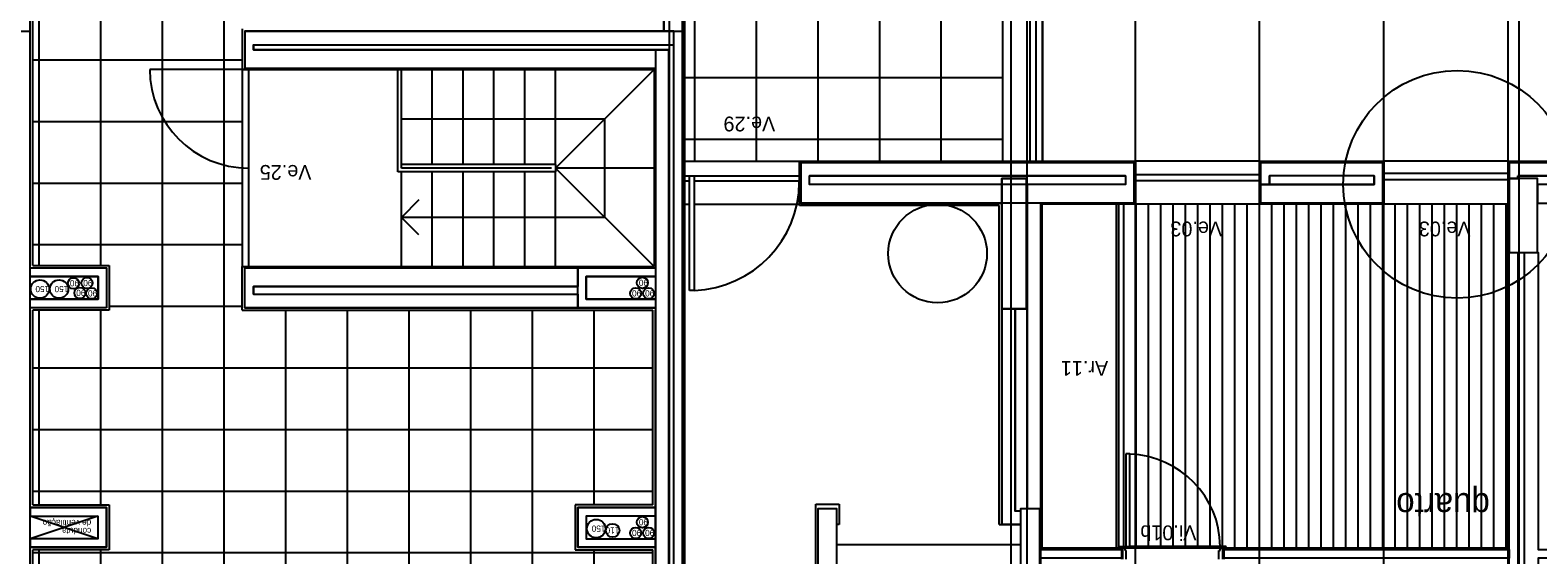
# Model space of a CAD drawing. Extents: x 1278 to 1356, y -253.7 to -224.
# Drawn here: x 1291.33 to 1303.56, y -235.12 to -230.86 of the extents above; entities that cross this region are included whole.
import ezdxf

# ---------------------------------------------------------------- set-up
doc = ezdxf.new("R2010")
doc.units = 0
for name, color, linetype in [('Level 1', 7, 'Continuous'), ('Level 10', 7, 'Continuous'), ('Level 13', 7, 'Continuous'), ('Level 2', 7, 'Continuous'), ('Level 21', 7, 'Continuous'), ('Level 25', 7, 'Continuous'), ('Level 3', 7, 'Continuous'), ('Level 4', 7, 'Continuous'), ('Level 40', 7, 'Continuous'), ('Level 41', 7, 'Continuous'), ('Level 60', 7, 'Continuous'), ('Level 65', 7, 'Continuous'), ('Level 66', 7, 'Continuous'), ('Level 67', 7, 'Continuous'), ('Level 69', 7, 'Continuous'), ('Level 70', 7, 'Continuous'), ('Level 93', 7, 'Continuous')]:
    doc.layers.add(name, color=color, linetype=linetype)

msp = doc.modelspace()

# ---------------------------------------------------------------- linework, layer by layer
at = {"layer": 'Level 1'}
for p, q in [((1291.334, -239.254), (1291.334, -228.594)), ((1296.473, -228.594), (1296.473, -230.87)), ((1296.623, -236.569), (1296.623, -228.594)), ((1287.754, -230.87), (1291.334, -230.87)), ((1293.074, -230.87), (1296.623, -230.87)), ((1293.074, -230.87), (1293.074, -231.17)), ((1296.553, -236.639), (1296.553, -230.87)), ((1293.144, -230.98), (1296.553, -230.98)), ((1293.144, -230.98), (1293.144, -231.02)), ((1293.144, -231.02), (1296.514, -231.02)), ((1296.404, -231.02), (1296.404, -233.134)), ((1296.514, -231.02), (1296.514, -232.974)), ((1293.074, -231.17), (1296.404, -231.17)), ((1297.583, -232.264), (1297.583, -231.934)), ((1300.287, -231.934), (1300.287, -232.264)), ((1301.314, -231.934), (1302.302, -231.934)), ((1301.314, -232.264), (1301.314, -231.934)), ((1302.302, -231.934), (1302.302, -232.264)), ((1303.329, -231.934), (1304.317, -231.934)), ((1297.653, -232.114), (1297.653, -232.044)), ((1300.217, -232.044), (1300.217, -232.114)), ((1301.384, -232.114), (1301.384, -232.044)), ((1302.232, -232.044), (1302.232, -232.114)), ((1303.399, -232.064), (1303.399, -232.044)), ((1299.213, -232.264), (1297.583, -232.264)), ((1299.213, -234.874), (1299.213, -232.264)), ((1300.287, -232.264), (1299.213, -232.264)), ((1299.42, -234.744), (1299.42, -232.264)), ((1302.302, -232.264), (1301.314, -232.264)), ((1293.074, -232.79), (1296.404, -232.79)), ((1293.074, -233.114), (1293.074, -232.79)), ((1293.144, -232.94), (1295.774, -232.94)), ((1293.144, -233.004), (1293.144, -232.94)), ((1293.144, -233.004), (1295.774, -233.004)), ((1296.514, -236.689), (1296.514, -232.974)), ((1293.074, -233.114), (1296.404, -233.114)), ((1296.404, -236.799), (1296.404, -233.134)), ((1299.324, -234.764), (1299.324, -233.121)), ((1299.369, -234.874), (1299.213, -234.874)), ((1299.369, -234.764), (1299.323, -234.764)), ((1300.183, -235.075), (1299.53, -235.075)), ((1300.183, -235.065), (1300.183, -235.155)), ((1301.013, -235.065), (1301.013, -235.075)), ((1301.013, -235.065), (1301.013, -235.155))]:
    msp.add_line(p, q, dxfattribs=at)
msp.add_lwpolyline([(1303.329, -235.075), (1301.013, -235.075)], dxfattribs=at)
at = {"layer": 'Level 10'}
for p, q in [((1300.204, -235.065), (1300.204, -232.274)), ((1300.304, -235.065), (1300.304, -232.274)), ((1300.404, -235.065), (1300.404, -232.274)), ((1300.504, -235.065), (1300.504, -232.274)), ((1300.604, -235.065), (1300.604, -232.274)), ((1300.704, -235.065), (1300.704, -232.274)), ((1300.804, -235.065), (1300.804, -232.274)), ((1300.904, -235.065), (1300.904, -232.274)), ((1301.004, -235.065), (1301.004, -232.274)), ((1301.104, -235.065), (1301.104, -232.274)), ((1301.204, -235.065), (1301.204, -232.274)), ((1301.304, -235.065), (1301.304, -232.274)), ((1301.404, -235.065), (1301.404, -232.274)), ((1301.504, -235.065), (1301.504, -232.274)), ((1301.604, -235.065), (1301.604, -232.274)), ((1301.704, -235.065), (1301.704, -232.274)), ((1301.804, -235.065), (1301.804, -232.274)), ((1301.904, -235.065), (1301.904, -232.274)), ((1302.004, -235.065), (1302.004, -232.274)), ((1302.104, -235.065), (1302.104, -232.274)), ((1302.204, -235.065), (1302.204, -232.274)), ((1302.304, -235.065), (1302.304, -232.274)), ((1302.404, -235.065), (1302.404, -232.274)), ((1302.504, -235.065), (1302.504, -232.274)), ((1302.604, -235.065), (1302.604, -232.274)), ((1302.704, -235.065), (1302.704, -232.274)), ((1302.804, -235.065), (1302.804, -232.274)), ((1302.904, -235.065), (1302.904, -232.274)), ((1303.004, -235.065), (1303.004, -232.274)), ((1303.104, -235.065), (1303.104, -232.274)), ((1303.204, -235.065), (1303.204, -232.274)), ((1303.304, -235.065), (1303.304, -232.274)), ((1300.983, -235.065), (1300.213, -235.065))]:
    msp.add_line(p, q, dxfattribs=at)
at = {"layer": 'Level 13'}
for p, q in [((1293.104, -231.18), (1292.304, -231.18)), ((1293.054, -231.18), (1293.054, -232.78)), ((1293.104, -231.18), (1293.104, -232.78)), ((1300.143, -235.065), (1300.143, -232.274)), ((1300.163, -235.065), (1300.163, -232.274)), ((1300.218, -234.3), (1300.218, -235.05)), ((1300.253, -234.3), (1300.218, -234.3)), ((1300.253, -235.05), (1300.253, -234.3)), ((1300.163, -235.05), (1300.213, -235.05)), ((1300.163, -235.06), (1300.163, -235.05)), ((1300.168, -235.06), (1300.163, -235.06)), ((1300.168, -235.065), (1300.168, -235.06)), ((1300.213, -235.065), (1300.168, -235.065)), ((1300.193, -235.065), (1300.193, -235.155)), ((1300.213, -235.065), (1300.193, -235.065)), ((1300.213, -235.05), (1300.213, -235.065)), ((1300.213, -235.085), (1300.213, -235.065)), ((1300.223, -235.085), (1300.213, -235.085)), ((1300.218, -235.05), (1300.253, -235.05)), ((1300.223, -235.155), (1300.223, -235.085)), ((1300.973, -235.155), (1300.973, -235.085)), ((1300.973, -235.085), (1300.983, -235.085)), ((1301.033, -235.05), (1300.983, -235.05)), ((1300.983, -235.05), (1300.983, -235.065)), ((1300.983, -235.085), (1300.983, -235.065)), ((1300.983, -235.065), (1301.003, -235.065)), ((1300.983, -235.065), (1301.028, -235.065)), ((1301.003, -235.065), (1301.003, -235.155)), ((1301.028, -235.065), (1301.028, -235.06)), ((1301.028, -235.06), (1301.033, -235.06)), ((1301.033, -235.06), (1301.033, -235.05))]:
    msp.add_line(p, q, dxfattribs=at)
msp.add_arc((1293.104, -231.18), 0.8, 180, 270, dxfattribs=at)
at = {"layer": 'Level 2'}
for p, q in [((1299.443, -231.924), (1299.443, -228.524)), ((1299.493, -231.924), (1299.493, -228.474)), ((1299.543, -231.924), (1299.543, -228.424)), ((1299.543, -228.424), (1299.543, -231.924)), ((1299.223, -231.924), (1299.223, -228.744)), ((1294.314, -232.01), (1294.314, -231.18)), ((1294.344, -231.98), (1294.344, -231.18)), ((1294.594, -231.95), (1294.594, -231.18)), ((1294.844, -231.95), (1294.844, -231.18)), ((1295.094, -231.95), (1295.094, -231.18)), ((1295.344, -231.95), (1295.344, -231.18)), ((1295.594, -231.95), (1295.594, -231.18)), ((1295.594, -231.98), (1296.394, -231.18)), ((1294.344, -231.58), (1295.994, -231.58)), ((1295.994, -232.38), (1295.994, -231.58)), ((1296.643, -231.924), (1297.573, -231.924)), ((1301.304, -231.924), (1300.297, -231.924)), ((1303.319, -231.924), (1302.312, -231.924)), ((1295.594, -232.01), (1294.314, -232.01)), ((1295.594, -231.95), (1294.344, -231.95)), ((1295.562, -231.98), (1294.344, -231.98)), ((1294.344, -232.78), (1294.344, -232.01)), ((1294.594, -232.78), (1294.594, -232.01)), ((1294.844, -232.78), (1294.844, -232.01)), ((1295.094, -232.78), (1295.094, -232.01)), ((1295.344, -232.78), (1295.344, -232.01)), ((1295.594, -231.95), (1295.594, -232.01)), ((1296.394, -231.98), (1295.594, -231.98)), ((1295.594, -231.98), (1296.394, -232.78)), ((1295.594, -232.78), (1295.594, -232.01)), ((1296.643, -232.044), (1297.573, -232.044)), ((1296.681, -232.974), (1296.681, -232.044)), ((1296.681, -232.044), (1296.721, -232.044)), ((1296.721, -232.974), (1296.721, -232.044)), ((1301.304, -232.034), (1300.297, -232.034)), ((1303.319, -232.024), (1302.312, -232.024)), ((1296.643, -232.084), (1296.681, -232.084)), ((1296.721, -232.084), (1297.573, -232.084)), ((1301.304, -232.084), (1300.297, -232.084)), ((1303.319, -232.074), (1302.312, -232.074)), ((1294.485, -232.239), (1294.344, -232.38)), ((1296.643, -232.274), (1296.681, -232.274)), ((1296.721, -232.274), (1297.573, -232.274)), ((1301.304, -232.274), (1300.297, -232.274)), ((1303.319, -232.274), (1302.312, -232.274)), ((1294.485, -232.522), (1294.344, -232.38)), ((1295.994, -232.38), (1294.344, -232.38)), ((1296.721, -232.974), (1296.681, -232.974)), ((1299.369, -235.039), (1297.873, -235.039))]:
    msp.add_line(p, q, dxfattribs=at)
msp.add_circle((1298.693, -232.674), 0.4, dxfattribs=at)
at = {"layer": 'Level 21'}
for p, q in [((1291.404, -228.744), (1291.404, -232.77)), ((1291.904, -228.744), (1291.904, -232.77)), ((1292.404, -228.744), (1292.404, -239.104)), ((1292.904, -228.744), (1292.904, -239.104)), ((1296.723, -231.924), (1296.723, -228.744)), ((1297.223, -231.924), (1297.223, -228.744)), ((1297.723, -231.924), (1297.723, -228.744)), ((1298.223, -231.924), (1298.223, -228.744)), ((1298.723, -231.924), (1298.723, -228.744)), ((1293.054, -231.104), (1291.354, -231.104)), ((1296.643, -231.244), (1299.223, -231.244)), ((1293.054, -231.604), (1291.354, -231.604)), ((1296.643, -231.744), (1299.223, -231.744)), ((1293.054, -232.104), (1291.354, -232.104)), ((1293.054, -232.604), (1291.354, -232.604)), ((1291.404, -233.134), (1291.404, -234.714)), ((1291.904, -233.134), (1291.904, -234.714)), ((1293.054, -233.104), (1291.974, -233.104)), ((1293.404, -233.134), (1293.404, -239.104)), ((1293.904, -233.134), (1293.904, -239.104)), ((1294.404, -233.134), (1294.404, -239.104)), ((1294.904, -233.134), (1294.904, -239.104)), ((1295.404, -233.134), (1295.404, -239.104)), ((1295.904, -233.134), (1295.904, -234.714)), ((1296.384, -233.604), (1291.354, -233.604)), ((1296.384, -234.104), (1291.354, -234.104)), ((1296.384, -234.604), (1291.354, -234.604)), ((1296.384, -235.104), (1291.354, -235.104)), ((1291.404, -235.078), (1291.404, -239.104)), ((1291.904, -235.078), (1291.904, -239.104)), ((1295.904, -235.078), (1295.904, -239.104))]:
    msp.add_line(p, q, dxfattribs=at)
at = {"layer": 'Level 25'}
msp.add_lwpolyline([(1299.213, -233.121), (1299.413, -233.121), (1299.413, -232.064), (1299.213, -232.064)], close=True, dxfattribs=at)
at = {"layer": 'Level 3'}
msp.add_ellipse((1296.68, -232.094), major_axis=(-0.891, 0), ratio=0.988242, start_param=1.616241, end_param=3.141592, dxfattribs=at)
at = {"layer": 'Level 4'}
msp.add_line((1300.983, -235.05), (1300.253, -235.05), dxfattribs=at)
msp.add_ellipse((1300.22, -235.05), major_axis=(-0.763, 0), ratio=0.982661, start_param=3.141593, end_param=4.668897, dxfattribs=at)
at = {"layer": 'Level 41'}
for p, q in [((1291.883, -234.988), (1291.334, -234.804)), ((1291.883, -234.804), (1291.334, -234.988))]:
    msp.add_line(p, q, dxfattribs=at)
for centre, radius in [((1291.413, -232.962), 0.075), ((1291.568, -232.962), 0.075), ((1291.685, -232.915), 0.045), ((1291.794, -232.913), 0.045), ((1296.299, -232.911), 0.045), ((1291.737, -232.993), 0.045), ((1291.832, -232.997), 0.045), ((1296.244, -232.997), 0.045), ((1296.35, -232.997), 0.045), ((1295.924, -234.906), 0.075), ((1296.057, -234.921), 0.055), ((1296.299, -234.854), 0.045), ((1296.244, -234.941), 0.045), ((1296.35, -234.941), 0.045)]:
    msp.add_circle(centre, radius, dxfattribs=at)
at = {"layer": 'Level 65'}
for p, q in [((1291.354, -232.77), (1291.354, -228.574)), ((1296.643, -236.545), (1296.643, -228.574)), ((1293.054, -230.85), (1293.054, -231.18)), ((1293.054, -231.18), (1296.394, -231.18)), ((1296.394, -231.18), (1296.394, -232.78)), ((1296.643, -231.924), (1300.297, -231.924)), ((1297.573, -232.284), (1297.573, -231.924)), ((1300.297, -231.924), (1300.297, -232.274)), ((1301.304, -232.274), (1301.304, -231.924)), ((1301.304, -231.924), (1302.312, -231.924)), ((1302.312, -231.924), (1302.312, -232.274)), ((1303.319, -231.924), (1304.327, -231.924)), ((1299.193, -232.284), (1297.573, -232.284)), ((1299.193, -234.874), (1299.193, -232.284)), ((1300.297, -232.274), (1299.54, -232.274)), ((1299.54, -235.065), (1299.54, -232.274)), ((1302.312, -232.274), (1301.304, -232.274)), ((1303.319, -235.065), (1303.319, -232.274)), ((1291.354, -232.77), (1291.974, -232.77)), ((1291.974, -232.77), (1291.974, -233.134)), ((1293.054, -232.78), (1296.394, -232.78)), ((1293.054, -233.134), (1293.054, -232.78)), ((1291.974, -233.134), (1291.354, -233.134)), ((1291.354, -234.714), (1291.354, -233.134)), ((1293.054, -233.134), (1296.384, -233.134)), ((1296.384, -234.714), (1296.384, -233.134)), ((1291.354, -234.714), (1291.973, -234.714)), ((1291.973, -234.714), (1291.973, -235.078)), ((1296.384, -234.714), (1295.754, -234.714)), ((1295.754, -234.714), (1295.754, -235.078)), ((1297.704, -234.708), (1297.894, -234.708)), ((1297.704, -236.545), (1297.704, -234.708)), ((1297.894, -234.708), (1297.894, -234.874)), ((1297.894, -234.874), (1297.873, -234.874)), ((1299.193, -234.874), (1299.213, -234.874)), ((1291.973, -235.078), (1291.354, -235.078)), ((1291.354, -239.274), (1291.354, -235.078)), ((1295.754, -235.078), (1296.384, -235.078)), ((1296.384, -236.819), (1296.384, -235.078)), ((1300.183, -235.065), (1299.54, -235.065))]:
    msp.add_line(p, q, dxfattribs=at)
msp.add_lwpolyline([(1303.319, -235.065), (1301.013, -235.065)], dxfattribs=at)
at = {"layer": 'Level 66'}
for p, q in [((1297.583, -231.934), (1300.287, -231.934)), ((1303.329, -235.075), (1303.329, -231.934)), ((1300.217, -232.044), (1297.653, -232.044)), ((1302.232, -232.044), (1301.384, -232.044)), ((1304.247, -232.044), (1303.399, -232.044)), ((1300.217, -232.114), (1297.653, -232.114)), ((1302.232, -232.114), (1301.384, -232.114)), ((1304.247, -232.114), (1303.559, -232.114)), ((1299.53, -243.584), (1299.53, -232.264)), ((1303.4, -236.221), (1303.4, -232.664)), ((1303.452, -236.221), (1303.452, -232.664)), ((1291.334, -232.79), (1291.954, -232.79)), ((1291.954, -232.79), (1291.954, -233.114)), ((1295.774, -233.114), (1295.774, -232.79)), ((1303.452, -236.352), (1303.452, -232.794)), ((1295.844, -233.044), (1295.844, -232.86)), ((1295.844, -232.86), (1296.404, -232.86)), ((1296.404, -233.044), (1295.844, -233.044)), ((1291.954, -233.114), (1291.334, -233.114)), ((1291.334, -234.734), (1291.953, -234.734)), ((1291.953, -234.734), (1291.953, -235.058)), ((1296.404, -234.734), (1295.774, -234.734)), ((1295.774, -234.734), (1295.774, -235.058)), ((1296.404, -234.804), (1295.844, -234.804)), ((1295.844, -234.804), (1295.844, -234.988)), ((1295.844, -234.988), (1296.404, -234.988)), ((1291.953, -235.058), (1291.334, -235.058)), ((1295.774, -235.058), (1296.404, -235.058))]:
    msp.add_line(p, q, dxfattribs=at)
for points in [[(1299.413, -233.121), (1299.213, -233.121), (1299.213, -232.064), (1299.413, -232.064)], [(1303.329, -232.664), (1303.559, -232.664), (1303.559, -232.064), (1303.329, -232.064)], [(1303.329, -232.664), (1303.559, -232.664), (1303.559, -232.064), (1303.329, -232.064)], [(1291.884, -233.044), (1291.334, -233.044), (1291.334, -232.86), (1291.884, -232.86)], [(1299.519, -234.744), (1299.519, -236.639), (1297.724, -236.639), (1297.724, -234.744), (1297.874, -234.744), (1297.874, -236.439), (1299.369, -236.439), (1299.369, -234.744)], [(1291.883, -234.988), (1291.334, -234.988), (1291.334, -234.804), (1291.883, -234.804)]]:
    msp.add_lwpolyline(points, close=True, dxfattribs=at)
at = {"layer": 'Level 67'}
msp.add_line((1296.404, -232.86), (1296.404, -233.044), dxfattribs=at)
for points in [[(1291.184, -239.254), (1291.334, -239.254), (1291.334, -228.594), (1291.184, -228.594), (1291.184, -230.87), (1291.224, -230.87), (1291.224, -233.114), (1291.184, -233.114)], [(1296.473, -230.87), (1296.473, -228.594), (1296.623, -228.594), (1296.623, -236.569), (1297.724, -236.569), (1297.724, -236.639), (1296.553, -236.639), (1296.553, -230.87)], [(1296.553, -230.87), (1293.074, -230.87), (1293.074, -231.17), (1296.404, -231.17), (1296.404, -236.799), (1299.181, -236.799), (1299.181, -243.914), (1301.224, -243.914), (1301.224, -243.584), (1299.519, -243.584), (1299.519, -243.734), (1301.154, -243.734), (1301.154, -243.804), (1299.291, -243.804), (1299.291, -236.689), (1296.514, -236.689), (1296.514, -231.17), (1296.514, -231.02), (1293.144, -231.02), (1293.144, -230.98), (1296.553, -230.98)], [(1299.42, -234.744), (1299.53, -234.744), (1299.53, -232.264), (1300.287, -232.264), (1300.287, -231.934), (1297.583, -231.934), (1297.583, -232.264), (1299.213, -232.264), (1299.213, -232.114), (1297.653, -232.114), (1297.653, -232.044), (1300.217, -232.044), (1300.217, -232.114), (1299.42, -232.114)], [(1302.302, -231.934), (1302.302, -232.264), (1301.314, -232.264), (1301.314, -232.114), (1302.232, -232.114), (1302.232, -232.044), (1301.384, -232.044), (1301.384, -232.114), (1301.314, -232.114), (1301.314, -231.934)], [(1303.399, -232.044), (1304.247, -232.044), (1304.247, -232.114), (1303.559, -232.114), (1303.559, -232.264), (1304.317, -232.264), (1304.317, -231.934), (1303.329, -231.934), (1303.329, -232.064), (1303.399, -232.064)], [(1303.4, -236.221), (1303.329, -236.221), (1303.329, -232.664), (1303.4, -232.664)], [(1304.213, -235.075), (1304.213, -235.145), (1303.562, -235.145), (1303.562, -236.221), (1303.452, -236.221), (1303.452, -232.664), (1303.562, -232.664), (1303.562, -235.075)], [(1291.954, -233.114), (1291.334, -233.114), (1291.334, -233.044), (1291.884, -233.044), (1291.884, -232.86), (1291.334, -232.86), (1291.334, -232.79), (1291.954, -232.79)], [(1295.774, -233.114), (1293.074, -233.114), (1293.074, -232.79), (1295.774, -232.79), (1295.774, -232.94), (1293.144, -232.94), (1293.144, -233.004), (1295.774, -233.004)], [(1296.404, -233.114), (1295.774, -233.114), (1295.774, -232.79), (1296.404, -232.79), (1296.404, -232.86), (1295.844, -232.86), (1295.844, -233.044), (1296.404, -233.044)], [(1299.323, -234.874), (1299.369, -234.874), (1299.369, -234.764), (1299.323, -234.764), (1299.323, -233.121), (1299.213, -233.121), (1299.213, -234.874)], [(1291.334, -235.058), (1291.953, -235.058), (1291.953, -234.734), (1291.334, -234.734), (1291.334, -234.804), (1291.883, -234.804), (1291.883, -234.988), (1291.334, -234.988)], [(1296.404, -235.058), (1295.774, -235.058), (1295.774, -234.734), (1296.404, -234.734), (1296.404, -234.804), (1295.844, -234.804), (1295.844, -234.988), (1296.404, -234.988)], [(1300.183, -235.075), (1300.183, -235.145), (1299.53, -235.145), (1299.53, -235.075)], [(1303.329, -235.075), (1303.329, -235.145), (1301.013, -235.145), (1301.013, -235.075)]]:
    msp.add_lwpolyline(points, close=True, dxfattribs=at)
at = {"layer": 'Level 69'}
msp.add_circle((1302.907, -232.112), 0.924, dxfattribs=at)
at = {"layer": 'Level 70'}
for p, q in [((1296.519, -250.792), (1296.519, -225.567)), ((1299.42, -250.792), (1299.42, -225.567)), ((1303.409, -250.792), (1303.409, -229.609))]:
    msp.add_line(p, q, dxfattribs=at)
at = {"layer": 'Level 93'}
for p, q in [((1299.289, -235.304), (1299.289, -224.312)), ((1300.297, -235.304), (1300.297, -224.312)), ((1301.304, -235.304), (1301.304, -224.312)), ((1302.312, -235.304), (1302.312, -224.312)), ((1303.319, -235.304), (1303.319, -224.312))]:
    msp.add_line(p, q, dxfattribs=at)

# ---------------------------------------------------------------- texts
at = {"layer": 'Level 40'}
for s, p in [('Ve.29', (1297.376, -231.562)), ('Ve.25', (1293.615, -231.955)), ('Ve.03', (1301, -232.414)), ('Ve.03', (1303.015, -232.414)), ('Ar.11', (1300.076, -233.545)), ('Vi.01b', (1300.792, -234.88))]:
    msp.add_text(s, height=0.12, rotation=180, dxfattribs=at).set_placement(p)
at = {"layer": 'Level 41'}
for s, p in [('90', (1291.73, -232.89)), ('90', (1291.839, -232.888)), ('90', (1296.344, -232.886)), ('150', (1291.488, -232.937)), ('150', (1291.643, -232.937)), ('90', (1291.782, -232.968)), ('90', (1291.877, -232.972)), ('90', (1296.289, -232.972)), ('90', (1296.395, -232.972)), ('de ventilação ', (1291.829, -234.835)), ('150', (1295.999, -234.881)), ('90', (1296.344, -234.829)), ('conduta', (1291.829, -234.9)), ('110', (1296.112, -234.896)), ('90', (1296.289, -234.916)), ('90', (1296.395, -234.916))]:
    msp.add_text(s, height=0.05, rotation=180, dxfattribs=at).set_placement(p)
at = {"layer": 'Level 60'}
msp.add_text('quarto', height=0.2, rotation=180, dxfattribs=at).set_placement((1303.171, -234.618))

doc.saveas('drawing.dxf')
